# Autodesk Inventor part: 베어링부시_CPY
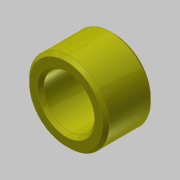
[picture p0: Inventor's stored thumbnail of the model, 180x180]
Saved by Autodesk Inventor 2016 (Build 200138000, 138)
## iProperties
Created: 2019-03
Part Number: 베어링부시_CPY
Material: 강철, 연강
Document SubType Name: Modeling
Designer: Administrator
Density: 1 g/cm^3
Appearance: 노란색
Author: mduedu
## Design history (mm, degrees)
sketch "스케치1"
  geometry: L1 (-7.5, 12.5)-(7.5, 12.5); L2 (7.5, 12.5)-(7.5, 8); L3 (7.5, 8)-(-7.5, 8); L4 (-7.5, 8)-(-7.5, 12.5); L5 (-7.5, 0)-(7.5, 0); 3 further points
  constraints: 10 end point, 2 midpoint, 2 parallel, 2 perpendicular, 2 vertical alignment, 1 coincident, 1 horizontal
  dimensions: "d0" = 16 diameter of L3 L5; "d2" = 25 diameter of L1 L5; "d3" = 15 distance of L1.start L1.end
revolve "회전1" sketch "스케치1" stored, may be unused: angle "d4" = 90 deg
chamfer "모따기1" distance "d5" = 1; stored, may be unused: second distance "d6" = 2, angle "d7" = 45 deg
chamfer "모따기2" distance "d8" = 1; stored, may be unused: second distance "d9" = 2, angle "d10" = 45 deg
node "솔리드1"
